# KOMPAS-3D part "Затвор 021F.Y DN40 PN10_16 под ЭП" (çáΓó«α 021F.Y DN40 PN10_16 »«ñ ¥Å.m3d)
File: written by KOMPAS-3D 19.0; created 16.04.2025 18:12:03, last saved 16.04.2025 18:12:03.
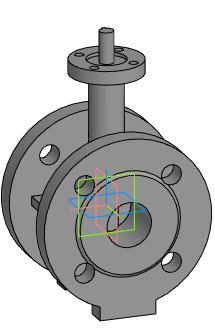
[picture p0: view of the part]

Document properties: Автор: Евгений; Полное имя файла: E:\Dendor Работа Сачек\3D для проекитирвщиков\1.6 Тип 021F.Y Затвор дисковый поворотный фланцевый\stp_Тип 021F.Y Затвор  DN40 PN10_16 под ЭП\Затвор 021F.Y DN40 PN10_16 под ЭП.m3d

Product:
- Part/product: Затвор 021F.Y DN40 PN10_16 под ЭП

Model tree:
1. Операция без истории:1  (labels: Затвор 021F.Y DN40 PN10_16 под ЭП)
